(* Logix 5000 project; controller ASI 1769-L16ER-BB1B rev 32.11; software revision 32.01 *)

TASK MainTask (continuous, watchdog 500 ms) : MainProgram

MODULES
   Local : 1769-L16ER-BB1B (PointIO 0, rev 32.11)
      asidualgateway : vendor 57 type 12 code 393 (Ethernet 192.168.137.15, rev 2.8, StandardDataDriven RPI 10 ms)
           asidualgateway:I1.Data[51]   // LDS 31-16 [Net 2]
           asidualgateway:I1.Data[0].4   // F0
           asidualgateway:I1.Data[0].5   // F1
           asidualgateway:I1.Data[0].6   // F2
           asidualgateway:I1.Data[0].7   // F3
           asidualgateway:I1.Data[16].4   // F0
           asidualgateway:I1.Data[16].5   // F1
           asidualgateway:I1.Data[16].6   // F2
           asidualgateway:I1.Data[16].7   // F3
           asidualgateway:I1.Data[33]   // LDS 15-0
           asidualgateway:I1.Data[37]   // LPS 15-0
           asidualgateway:I1.Data[41]   // LAS 15-0
           asidualgateway:I1.Data[45]   // LPF 15-0
           asidualgateway:I1.Data[52]   // LDS 15B-0 [Net 2]
           asidualgateway:I1.Data[55]   // LPS 31-16 [Net 2]
           asidualgateway:I1.Data[56]   // LPS 15B-0 [Net 2]
           asidualgateway:I1.Data[2]   // 10A, 11A, 8A, 9A
           asidualgateway:I1.Data[0]   // 2A, 3A, Flags, 1A
           asidualgateway:I1.Data[3]   // 14A, 15A, 12A, 13A
           asidualgateway:I1.Data[4]   // 18A, 19A, 16A, 17A
           asidualgateway:I1.Data[5]   // 22A, 23A, 20A, 21A
           asidualgateway:I1.Data[6]   // 26A, 27A, 24A, 25A
           asidualgateway:I1.Data[7]   // 30A, 31A, 28A, 29A
           asidualgateway:I1.Data[10]   // 10B, 11B, 8B, 9B
           asidualgateway:I1.Data[32]   // Diagnostic Bits
           asidualgateway:I1.Data[32].14   // Power Fail
           asidualgateway:I1.Data[49].14   // Power Fail
           asidualgateway:I1.Data[50]   // LDS 15-0 [Net 2]
           asidualgateway:I1.Data[32].15   // Offline
           asidualgateway:I1.Data[54]   // LPS 15-0 [Net 2]
           asidualgateway:I1.Data[58]   // LAS 15-0 [Net 2]
           asidualgateway:I1.Data[62]   // LPF 15-0 [Net 2]
           asidualgateway:I1.Data[59]   // LAS 31-16 [Net 2]
           asidualgateway:I1.Data[49].15   // Offline
           asidualgateway:I1.Data[17]   // 6A, 7A, 4A, 5A [Net 2]
           asidualgateway:I1.Data[32].8   // Configuration Error
           asidualgateway:I1.Data[32].9   // LDS.0
           asidualgateway:I1.Data[32].0   // Peripheral Fault
           asidualgateway:I1.Data[8]   // 2B, 3B, 0, 1B
           asidualgateway:I1.Data[100]   // Analog, Adr 30, Channel 3 [Net 2]
           asidualgateway:I1.Data[34]   // LDS 31-16
           asidualgateway:I1.Data[49].9   // LDS.0
           asidualgateway:I1.Data[36]   // LDS 31B-16B
           asidualgateway:I1.Data[40]   // LPS 31B-16B
           asidualgateway:I1.Data[35]   // LDS 15B-0
           asidualgateway:I1.Data[44]   // LAS 31B-16B
           asidualgateway:I1.Data[48]   // LPF 31B-16B
           asidualgateway:I1.Data[38]   // LPS 31-16
           asidualgateway:I1.Data[101]   // Analog, Adr 30, Channel 4 [Net 2]
           asidualgateway:I1.Data[49].0   // Peripheral Fault
           asidualgateway:I1.Data[25]   // 6B, 7B, 4B, 5B [Net 2]
           asidualgateway:I1.Data[49]   // Diagnostic Bits [Net 2]
           asidualgateway:I1.Data[39]   // LPS 15B-0
           asidualgateway:I1.Data[42]   // LAS 31-16
           asidualgateway:I1.Data[1]   // 6A, 7A, 4A, 5A
           asidualgateway:I1.Data[43]   // LAS 15B-0
           asidualgateway:I1.Data[9]   // 6B, 7B, 4B, 5B
           asidualgateway:I1.Data[46]   // LPF 31-16
           asidualgateway:I1.Data[47]   // LPF 15B-0
           asidualgateway:I1.Data[60]   // LAS 15B-0 [Net 2]
           asidualgateway:I1.Data[11]   // 14B, 15B, 12B, 13B
           asidualgateway:I1.Data[53]   // LDS 31B-16B [Net 2]
           asidualgateway:I1.Data[57]   // LPS 31B-16B [Net 2]
           asidualgateway:I1.Data[12]   // 18B, 19B, 16B, 17B
           asidualgateway:I1.Data[24]   // 2B, 3B, 0, 1B [Net 2]
           asidualgateway:I1.Data[63]   // LPF 31-16 [Net 2]
           asidualgateway:I1.Data[13]   // 22B, 23B, 20B, 21B
           asidualgateway:I1.Data[61]   // LAS 31B-16B [Net 2]
           asidualgateway:I1.Data[65]   // LPF 31B-16B [Net 2]
           asidualgateway:I1.Data[14]   // 26B, 27B, 24B, 25B
           asidualgateway:I1.Data[64]   // LPF 15B-0 [Net 2]
           asidualgateway:I1.Data[15]   // 30B, 31B, 28B, 29B
           asidualgateway:I1.Data[18]   // 10A, 11A, 8A, 9A [Net 2]
           asidualgateway:I1.Data[19]   // 14A, 15A, 12A, 13A [Net 2]
           asidualgateway:I1.Data[20]   // 18A, 19A, 16A, 17A [Net 2]
           asidualgateway:I1.Data[21]   // 22A, 23A, 20A, 21A [Net 2]
           asidualgateway:I1.Data[22]   // 26A, 27A, 24A, 25A [Net 2]
           asidualgateway:I1.Data[23]   // 30A, 31A, 28A, 29A [Net 2]
           asidualgateway:I1.Data[26]   // 10B, 11B, 8B, 9B [Net 2]
           asidualgateway:I1.Data[27]   // 14B, 15B, 12B, 13B [Net 2]
           asidualgateway:I1.Data[28]   // 18B, 19B, 16B, 17B [Net 2]
           asidualgateway:I1.Data[29]   // 22B, 23B, 20B, 21B [Net 2]
           asidualgateway:I1.Data[30]   // 26B, 27B, 24B, 25B [Net 2]
           asidualgateway:I1.Data[31]   // 30B, 31B, 28B, 29B [Net 2]
           asidualgateway:I1.Data[32].1   // Earth/Ground Fault
           asidualgateway:I1.Data[49].8   // Configuration Error
           asidualgateway:I1.Data[49].13   // Normal Operation
           asidualgateway:I1.Data[32].10   // Automatic Addressing Not Possible
           asidualgateway:I1.Data[32].11   // Automatic Addressing Available
           asidualgateway:I1.Data[32].13   // Normal Operation
           asidualgateway:I1.Data[49].10   // Automatic Addressing Not Possible
           asidualgateway:I1.Data[49].11   // Automatic Addressing Available
           asidualgateway:I1.Data[32].12   // Configuration Mode Active
           asidualgateway:I1.Data[49].1   // Earth/Ground Fault
           asidualgateway:I1.Data[16]   // 2A, 3A, Flags, 1A [Net 2]
           asidualgateway:I1.Data[66]   // Analog, Adr 27, Channel 1
           asidualgateway:I1.Data[67]   // Analog, Adr 27, Channel 2
           asidualgateway:I1.Data[68]   // Analog, Adr 27, Channel 3
           asidualgateway:I1.Data[69]   // Analog, Adr 27, Channel 4
           asidualgateway:I1.Data[70]   // Analog, Adr 28, Channel 1
           asidualgateway:I1.Data[71]   // Analog, Adr 28, Channel 2
           asidualgateway:I1.Data[72]   // Analog, Adr 28, Channel 3
           asidualgateway:I1.Data[73]   // Analog, Adr 28, Channel 4
           asidualgateway:I1.Data[74]   // Analog, Adr 29, Channel 1
           asidualgateway:I1.Data[75]   // Analog, Adr 29, Channel 2
           asidualgateway:I1.Data[76]   // Analog, Adr 29, Channel 3
           asidualgateway:I1.Data[77]   // Analog, Adr 29, Channel 4
           asidualgateway:I1.Data[78]   // Analog, Adr 30, Channel 1
           asidualgateway:I1.Data[79]   // Analog, Adr 30, Channel 2
           asidualgateway:I1.Data[80]   // Analog, Adr 30, Channel 3
           asidualgateway:I1.Data[81]   // Analog, Adr 30, Channel 4
           asidualgateway:I1.Data[82]   // Analog, Adr 31, Channel 1
           asidualgateway:I1.Data[83]   // Analog, Adr 31, Channel 2
           asidualgateway:I1.Data[84]   // Analog, Adr 31, Channel 3
           asidualgateway:I1.Data[49].12   // Configuration Mode Active
           asidualgateway:I1.Data[86]   // Analog, Adr 27, Channel 1 [Net 2]
           asidualgateway:I1.Data[87]   // Analog, Adr 27, Channel 2 [Net 2]
           asidualgateway:I1.Data[88]   // Analog, Adr 27, Channel 3 [Net 2]
           asidualgateway:I1.Data[89]   // Analog, Adr 27, Channel 4 [Net 2]
           asidualgateway:I1.Data[90]   // Analog, Adr 28, Channel 1 [Net 2]
           asidualgateway:I1.Data[91]   // Analog, Adr 28, Channel 2 [Net 2]
           asidualgateway:I1.Data[92]   // Analog, Adr 28, Channel 3 [Net 2]
           asidualgateway:I1.Data[93]   // Analog, Adr 28, Channel 4 [Net 2]
           asidualgateway:I1.Data[94]   // Analog, Adr 29, Channel 1 [Net 2]
           asidualgateway:I1.Data[95]   // Analog, Adr 29, Channel 2 [Net 2]
           asidualgateway:I1.Data[96]   // Analog, Adr 29, Channel 3 [Net 2]
           asidualgateway:I1.Data[97]   // Analog, Adr 29, Channel 4 [Net 2]
           asidualgateway:I1.Data[98]   // Analog, Adr 30, Channel 1 [Net 2]
           asidualgateway:I1.Data[102]   // Analog, Adr 31, Channel 1 [Net 2]
           asidualgateway:I1.Data[103]   // Analog, Adr 31, Channel 2 [Net 2]
           asidualgateway:I1.Data[104]   // Analog, Adr 31, Channel 3 [Net 2]
           asidualgateway:I1.Data[105]   // Analog, Adr 31, Channel 4 [Net 2]
           asidualgateway:I1.Data[85]   // Analog, Adr 31, Channel 4
           asidualgateway:I1.Data[99]   // Analog, Adr 30, Channel 2 [Net 2]
           asidualgateway:O1.Data[2]   // 10A, 11A, 8A, 9A
           asidualgateway:O1.Data[3]   // 14A, 15A, 12A, 13A
           asidualgateway:O1.Data[4]   // 18A, 19A, 16A, 17A
           asidualgateway:O1.Data[5]   // 22A, 23A, 20A, 21A
           asidualgateway:O1.Data[6]   // 26A, 27A, 24A, 25A
           asidualgateway:O1.Data[7]   // 30A, 31A, 28A, 29A
           asidualgateway:O1.Data[10]   // 10B, 11B, 8B, 9B
           asidualgateway:O1.Data[71]   // Analog, Adr 31, Channel 4 [Net 2]
           asidualgateway:O1.Data[68]   // Analog, Adr 31, Channel 1 [Net 2]
           asidualgateway:O1.Data[65]   // Analog, Adr 30, Channel 2 [Net 2]
           asidualgateway:O1.Data[59]   // Analog, Adr 28, Channel 4 [Net 2]
           asidualgateway:O1.Data[19]   // 14A, 15A, 12A, 13A [Net 2]
           asidualgateway:O1.Data[70]   // Analog, Adr 31, Channel 3 [Net 2]
           asidualgateway:O1.Data[0]   // 2A, 3A, 0, 1A
           asidualgateway:O1.Data[8]   // 2B, 3B, 0, 1B
           asidualgateway:O1.Data[69]   // Analog, Adr 31, Channel 2 [Net 2]
           asidualgateway:O1.Data[60]   // Analog, Adr 29, Channel 1 [Net 2]
           asidualgateway:O1.Data[66]   // Analog, Adr 30, Channel 3 [Net 2]
           asidualgateway:O1.Data[61]   // Analog, Adr 29, Channel 2 [Net 2]
           asidualgateway:O1.Data[20]   // 18A, 19A, 16A, 17A [Net 2]
           asidualgateway:O1.Data[1]   // 6A, 7A, 4A, 5A
           asidualgateway:O1.Data[9]   // 6B, 7B, 4B, 5B
           asidualgateway:O1.Data[16]   // 2A, 3A, 0, 1A [Net 2]
           asidualgateway:O1.Data[24]   // 2B, 3B, 0, 1B [Net 2]
           asidualgateway:O1.Data[14]   // 26B, 27B, 24B, 25B
           asidualgateway:O1.Data[15]   // 30B, 31B, 28B, 29B
           asidualgateway:O1.Data[11]   // 14B, 15B, 12B, 13B
           asidualgateway:O1.Data[12]   // 18B, 19B, 16B, 17B
           asidualgateway:O1.Data[13]   // 22B, 23B, 20B, 21B
           asidualgateway:O1.Data[67]   // Analog, Adr 30, Channel 4 [Net 2]
           asidualgateway:O1.Data[62]   // Analog, Adr 29, Channel 3 [Net 2]
           asidualgateway:O1.Data[17]   // 6A, 7A, 4A, 5A [Net 2]
           asidualgateway:O1.Data[63]   // Analog, Adr 29, Channel 4 [Net 2]
           asidualgateway:O1.Data[64]   // Analog, Adr 30, Channel 1 [Net 2]
           asidualgateway:O1.Data[18]   // 10A, 11A, 8A, 9A [Net 2]
           asidualgateway:O1.Data[25]   // 6B, 7B, 4B, 5B [Net 2]
           asidualgateway:O1.Data[26]   // 10B, 11B, 8B, 9B [Net 2]
           asidualgateway:O1.Data[32]   // Analog, Adr 27, Channel 1
           asidualgateway:O1.Data[33]   // Analog, Adr 27, Channel 2
           asidualgateway:O1.Data[34]   // Analog, Adr 27, Channel 3
           asidualgateway:O1.Data[35]   // Analog, Adr 27, Channel 4
           asidualgateway:O1.Data[36]   // Analog, Adr 28, Channel 1
           asidualgateway:O1.Data[37]   // Analog, Adr 28, Channel 2
           asidualgateway:O1.Data[38]   // Analog, Adr 28, Channel 3
           asidualgateway:O1.Data[39]   // Analog, Adr 28, Channel 4
           asidualgateway:O1.Data[40]   // Analog, Adr 29, Channel 1
           asidualgateway:O1.Data[41]   // Analog, Adr 29, Channel 2
           asidualgateway:O1.Data[42]   // Analog, Adr 29, Channel 3
           asidualgateway:O1.Data[43]   // Analog, Adr 29, Channel 4
           asidualgateway:O1.Data[44]   // Analog, Adr 30, Channel 1
           asidualgateway:O1.Data[45]   // Analog, Adr 30, Channel 2
           asidualgateway:O1.Data[46]   // Analog, Adr 30, Channel 3
           asidualgateway:O1.Data[47]   // Analog, Adr 30, Channel 4
           asidualgateway:O1.Data[21]   // 22A, 23A, 20A, 21A [Net 2]
           asidualgateway:O1.Data[22]   // 26A, 27A, 24A, 25A [Net 2]
           asidualgateway:O1.Data[23]   // 30A, 31A, 28A, 29A [Net 2]
           asidualgateway:O1.Data[27]   // 14B, 15B, 12B, 13B [Net 2]
           asidualgateway:O1.Data[28]   // 18B, 19B, 16B, 17B [Net 2]
           asidualgateway:O1.Data[29]   // 22B, 23B, 20B, 21B [Net 2]
           asidualgateway:O1.Data[30]   // 26B, 27B, 24B, 25B [Net 2]
           asidualgateway:O1.Data[31]   // 30B, 31B, 28B, 29B [Net 2]
           asidualgateway:O1.Data[48]   // Analog, Adr 31, Channel 1
           asidualgateway:O1.Data[49]   // Analog, Adr 31, Channel 2
           asidualgateway:O1.Data[50]   // Analog, Adr 31, Channel 3
           asidualgateway:O1.Data[51]   // Analog, Adr 31, Channel 4
           asidualgateway:O1.Data[52]   // Analog, Adr 27, Channel 1 [Net 2]
           asidualgateway:O1.Data[53]   // Analog, Adr 27, Channel 2 [Net 2]
           asidualgateway:O1.Data[54]   // Analog, Adr 27, Channel 3 [Net 2]
           asidualgateway:O1.Data[55]   // Analog, Adr 27, Channel 4 [Net 2]
           asidualgateway:O1.Data[56]   // Analog, Adr 28, Channel 1 [Net 2]
           asidualgateway:O1.Data[57]   // Analog, Adr 28, Channel 2 [Net 2]
           asidualgateway:O1.Data[58]   // Analog, Adr 28, Channel 3 [Net 2]
      Discrete_IO : Embedded (PointIO 1, rev 32.11, Output RPI 20 ms)
END_MODULES

TYPE CTT2Command :
STRUCT
   Address : SINT;   // 1-31=1A-31A or 32-62= 31B-62B
   Command : SINT;   // 18=Read Venddor Specific Object
   Object : SINT;
   Length : SINT;
END_STRUCT
END_TYPE

TYPE Get_Member :
STRUCT
   Address : SINT;   // 1-31 = Address 1A-31A, 32-62 = Address 1B-31B
   Null : SINT;
END_STRUCT
END_TYPE

TYPE PF_Parameters :
STRUCT
   ADR_1A : SINT;
   ADR_2A : SINT;
   ADR_3A : SINT;
   ADR_4A : SINT;
   ADR_5A : SINT;
   ADR_6A : SINT;
   ADR_7A : SINT;
   ADR_8A : SINT;
   ADR_9A : SINT;
   ADR_10A : SINT;
   ADR_11A : SINT;
   ADR_12A : SINT;
   ADR_13A : SINT;
   ADR_14A : SINT;
   ADR_15A : SINT;
   ADR_16A : SINT;
   ADR_17A : SINT;
   ADR_18A : SINT;
   ADR_19A : SINT;
   ADR_20A : SINT;
   ADR_21A : SINT;
   ADR_22A : SINT;
   ADR_23A : SINT;
   ADR_24A : SINT;
   ADR_25A : SINT;
   ADR_26A : SINT;
   ADR_27A : SINT;
   ADR_28A : SINT;
   ADR_29A : SINT;
   ADR_30A : SINT;
   ADR_31A : SINT;
   ADR_1B : SINT;
   ADR_2B : SINT;
   ADR_3B : SINT;
   ADR_4B : SINT;
   ADR_5B : SINT;
   ADR_6B : SINT;
   ADR_7B : SINT;
   ADR_8B : SINT;
   ADR_9B : SINT;
   ADR_10B : SINT;
   ADR_11B : SINT;
   ADR_12B : SINT;
   ADR_13B : SINT;
   ADR_14B : SINT;
   ADR_15B : SINT;
   ADR_16B : SINT;
   ADR_17B : SINT;
   ADR_18B : SINT;
   ADR_19B : SINT;
   ADR_20B : SINT;
   ADR_21B : SINT;
   ADR_22B : SINT;
   ADR_23B : SINT;
   ADR_24B : SINT;
   ADR_25B : SINT;
   ADR_26B : SINT;
   ADR_27B : SINT;
   ADR_28B : SINT;
   ADR_29B : SINT;
   ADR_30B : SINT;
   ADR_31B : SINT;
END_STRUCT
END_TYPE

TYPE PF_Safety_Monitor_Diagnostics :
STRUCT
   NA : SINT;
   NA1 : SINT;
   NA2 : SINT;
   Status : SINT;   // Bit 0=Mode(0-config, 1=protect) Bit 4 Status S12 Bit 5 Status S21 Bit 6 Status S32 Bit 7 Status S41
   OSSD_2_1 : SINT;
   OSSD_4_3 : SINT;
   OSSD_6_5 : SINT;
   OSSD_8_7 : SINT;
   OSSD_10_9 : SINT;
   OSSD_12_11 : SINT;
   OSSD_14_13 : SINT;
   OSSD_16_15 : SINT;
   Device_Index_Present : SINT[32];   // Indexes that are present from 0 to 255
   Device_Index_Color : SINT[128];   // Two Indexes per byte, bits 0-3 device 1, bits 4-7 device 2
END_STRUCT
END_TYPE

TYPE Set_Parameter :
STRUCT
   Address : SINT;   // 1-31=Address 1-31, 32-62=Address 1B-31B
   Parameter : SINT;   // Parameter to Set
END_STRUCT
END_TYPE

TYPE Set_Ramp :
STRUCT
   Address : SINT;   // 1-31=Address 1-31, 32-62=Address 1B-31B
   Ramp : SINT;   // 0=No Ramp, 1=50ms, 2=100ms, 3=200ms, 4=300ms, 5=500ms, 6=1s, 7=1.5s
END_STRUCT
END_TYPE

ADD_ON_INSTRUCTION PF_Safety_Diag_KE5   (* revision 1.0, vendor Pepperl+Fuchs *)
// Reads diagnostics from a safety monitor on a VBg-EP1-KE5...
VAR_INPUT
   Trigger : BOOL; {visible}
   Safety_Monitor_Address : SINT; {visible}   // The address the safety monitor has been set to. Use 0 for Internal safety monitors
   ASi_Network : SINT; {visible}   // Which AS-i network is mailbox command being sent to. 0/1 is network 1, 2 is network 2
   Object : SINT; {visible}
END_VAR
VAR_OUTPUT
   EN : BOOL; {access Read Only, visible}   // Instruction is enabled
   DN : BOOL; {access Read Only, visible}   // DN bit, When on the instruction has completed. Check ER bit for Error
   ER : BOOL; {access Read Only, visible}   // If the DN bit is on and ER bit is off then command was successful. If ER bit is on then check status byte
END_VAR
VAR_IN_OUT
   ReadStringCmdMSG : MESSAGE; {required}
   ReadStringResponseMSG : MESSAGE; {required}
   Source : SINT[4]; {required}
   Destination : SINT[256]; {required}
END_VAR
VAR_OUTPUT
   State_of_OSSD_1 : SINT; {access Read Only, visible}   // 0 Green 1 Green flashing 2 Yellow 3 Yellow flashing 4 Red 5 Red flashing 6 Grey (OSSD not used) 7 Reserved
   State_of_OSSD_2 : SINT; {access Read Only, visible}   // 0 Green 1 Green flashing 2 Yellow 3 Yellow flashing 4 Red 5 Red flashing 6 Grey (OSSD not used) 7 Reserved
   State_of_OSSD_3 : SINT; {access Read Only, visible}   // 0 Green 1 Green flashing 2 Yellow 3 Yellow flashing 4 Red 5 Red flashing 6 Grey (OSSD not used) 7 Reserved
   State_of_OSSD_4 : SINT; {access Read Only, visible}   // 0 Green 1 Green flashing 2 Yellow 3 Yellow flashing 4 Red 5 Red flashing 6 Grey (OSSD not used) 7 Reserved
   State_of_OSSD_5 : SINT; {access Read Only, visible}   // 0 Green 1 Green flashing 2 Yellow 3 Yellow flashing 4 Red 5 Red flashing 6 Grey (OSSD not used) 7 Reserved
   State_of_OSSD_6 : SINT; {access Read Only, visible}   // 0 Green 1 Green flashing 2 Yellow 3 Yellow flashing 4 Red 5 Red flashing 6 Grey (OSSD not used) 7 Reserved
   State_of_OSSD_7 : SINT; {access Read Only, visible}   // 0 Green 1 Green flashing 2 Yellow 3 Yellow flashing 4 Red 5 Red flashing 6 Grey (OSSD not used) 7 Reserved
   State_of_OSSD_8 : SINT; {access Read Only, visible}   // 0 Green 1 Green flashing 2 Yellow 3 Yellow flashing 4 Red 5 Red flashing 6 Grey (OSSD not used) 7 Reserved
   State_of_OSSD_9 : SINT; {access Read Only, visible}   // 0 Green 1 Green flashing 2 Yellow 3 Yellow flashing 4 Red 5 Red flashing 6 Grey (OSSD not used) 7 Reserved
   State_of_OSSD_10 : SINT; {access Read Only, visible}   // 0 Green 1 Green flashing 2 Yellow 3 Yellow flashing 4 Red 5 Red flashing 6 Grey (OSSD not used) 7 Reserved
   State_of_OSSD_11 : SINT; {access Read Only, visible}   // 0 Green 1 Green flashing 2 Yellow 3 Yellow flashing 4 Red 5 Red flashing 6 Grey (OSSD not used) 7 Reserved
   State_of_OSSD_12 : SINT; {access Read Only, visible}   // 0 Green 1 Green flashing 2 Yellow 3 Yellow flashing 4 Red 5 Red flashing 6 Grey (OSSD not used) 7 Reserved
   State_of_OSSD_13 : SINT; {access Read Only, visible}   // 0 Green 1 Green flashing 2 Yellow 3 Yellow flashing 4 Red 5 Red flashing 6 Grey (OSSD not used) 7 Reserved
   State_of_OSSD_14 : SINT; {access Read Only, visible}   // 0 Green 1 Green flashing 2 Yellow 3 Yellow flashing 4 Red 5 Red flashing 6 Grey (OSSD not used) 7 Reserved
   State_of_OSSD_15 : SINT; {access Read Only, visible}   // 0 Green 1 Green flashing 2 Yellow 3 Yellow flashing 4 Red 5 Red flashing 6 Grey (OSSD not used) 7 Reserved
   State_of_OSSD_16 : SINT; {access Read Only, visible}   // 0 Green 1 Green flashing 2 Yellow 3 Yellow flashing 4 Red 5 Red flashing 6 Grey (OSSD not used) 7 Reserved
END_VAR
VAR_IN_OUT
   Device_Presence : SINT[16]; {required}   // 1 bit for each device object used in safety monitor program
   Index_Colors : SINT[128]; {required}   // An array of diagnostic colors 0 Green 1 Green flashing 2 Yellow 3 Yellow flashing 4 Red 5 Red flashing 6 Gray
END_VAR
VAR_OUTPUT
   Last_Index : DINT; {access Read Only, visible}   // The number of diagnostic indexes returned
   Mode : BOOL; {access Read Only, visible}   // Off=Config Mode, On=Protected mode
   S12 : BOOL; {access Read Only, visible}
   S21 : BOOL; {access Read Only, visible}
   S32 : BOOL; {visible}
   S41 : BOOL; {visible}
   Error_Code : INT; {access Read Only, visible}
END_VAR
VAR
   oneshot : DINT; {access None}
   Null : SINT; {access None}
   Indexcolors : DINT; {access None}
   index0 : DINT; {access None}
   index1 : DINT; {access None}
   Color_Pointer : DINT; {access None}
   watchdog : TIMER := (PRE := 8000); {access None}
END_VAR

ROUTINE Logic   (* ladder *)
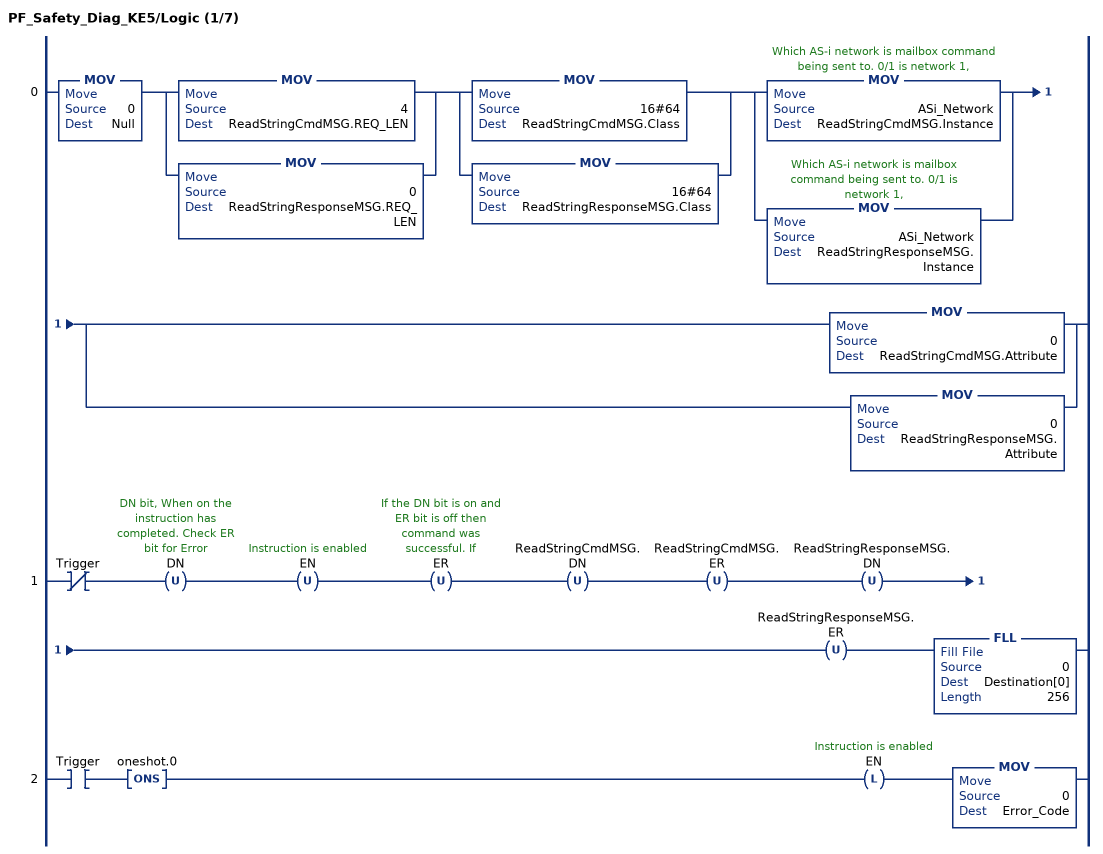
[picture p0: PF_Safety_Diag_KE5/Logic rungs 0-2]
   0: MOV(0,Null)[MOV(4,ReadStringCmdMSG.REQ_LEN) ,MOV(0,ReadStringResponseMSG.REQ_LEN) ][MOV(16#64,ReadStringCmdMSG.Class) ,MOV(16#64,ReadStringResponseMSG.Class) ][MOV(ASi_Network,ReadStringCmdMSG.Instance) ,MOV(ASi_Network,ReadStringResponseMSG.Instance) ][MOV(0,ReadStringCmdMSG.Attribute) ,MOV(0,ReadStringResponseMSG.Attribute) ];
   1: XIO(Trigger)OTU(DN)OTU(EN)OTU(ER)OTU(ReadStringCmdMSG.DN)OTU(ReadStringCmdMSG.ER)OTU(ReadStringResponseMSG.DN)OTU(ReadStringResponseMSG.ER)FLL(0,Destination[0],256);
   2: XIC(Trigger)ONS(oneshot.0)OTL(EN)MOV(0,Error_Code);
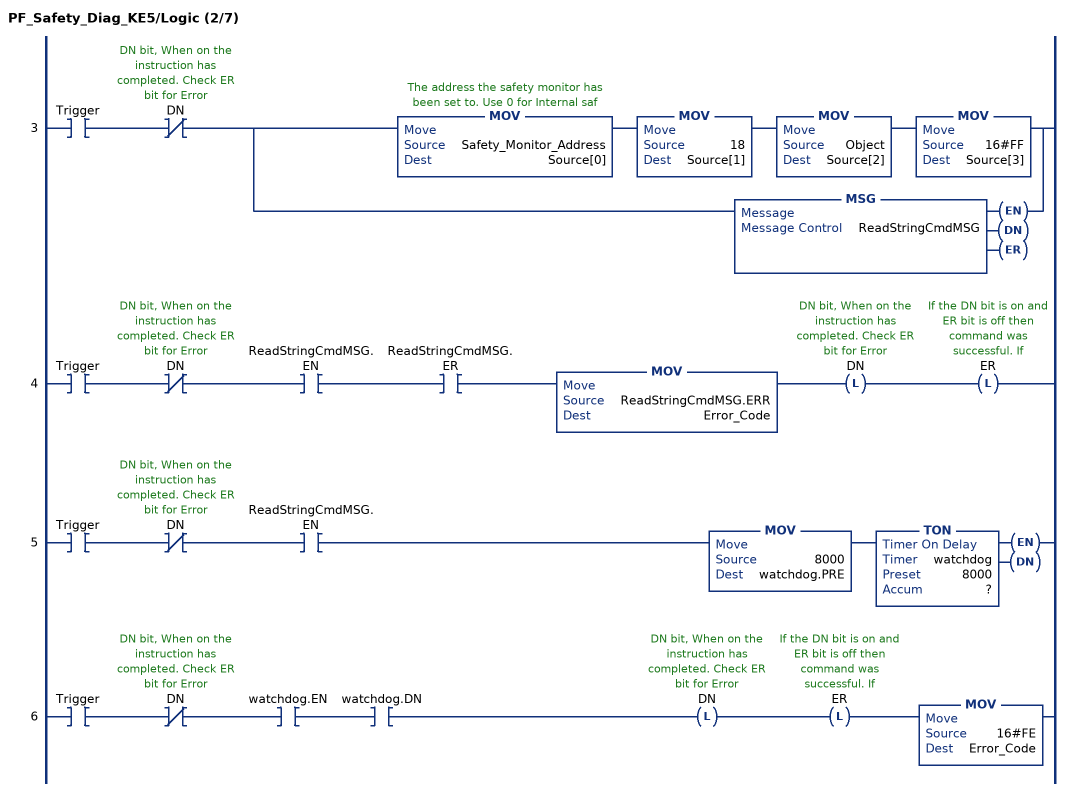
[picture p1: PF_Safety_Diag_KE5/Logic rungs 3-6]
   3: XIC(Trigger)XIO(DN)[MOV(Safety_Monitor_Address,Source[0]) MOV(18,Source[1]) MOV(Object,Source[2]) MOV(16#FF,Source[3]) ,MSG(ReadStringCmdMSG) ];
   4: XIC(Trigger)XIO(DN)XIC(ReadStringCmdMSG.EN)XIC(ReadStringCmdMSG.ER)MOV(ReadStringCmdMSG.ERR,Error_Code)OTL(DN)OTL(ER);
   5: XIC(Trigger)XIO(DN)XIC(ReadStringCmdMSG.EN)MOV(8000,watchdog.PRE)TON(watchdog,?,?);
   6: XIC(Trigger)XIO(DN)XIC(watchdog.EN)XIC(watchdog.DN)OTL(DN)OTL(ER)MOV(16#FE,Error_Code);
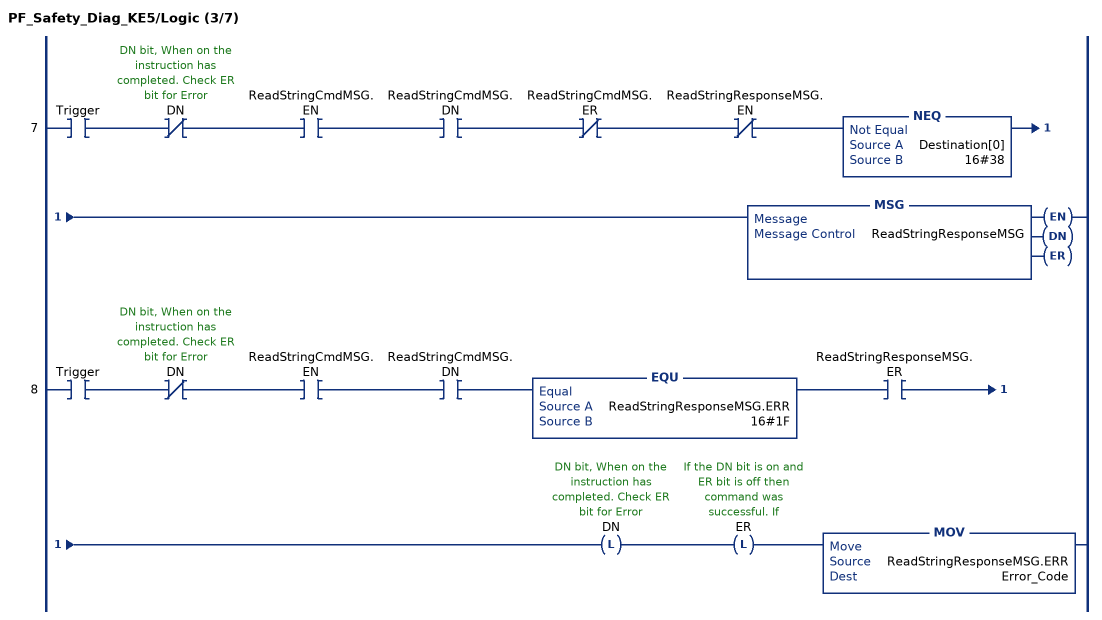
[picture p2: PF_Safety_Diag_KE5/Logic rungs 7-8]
   7: XIC(Trigger)XIO(DN)XIC(ReadStringCmdMSG.EN)XIC(ReadStringCmdMSG.DN)XIO(ReadStringCmdMSG.ER)XIO(ReadStringResponseMSG.EN)NEQ(Destination[0],16#38)MSG(ReadStringResponseMSG);
   8: XIC(Trigger)XIO(DN)XIC(ReadStringCmdMSG.EN)XIC(ReadStringCmdMSG.DN)EQU(ReadStringResponseMSG.ERR,16#1F)XIC(ReadStringResponseMSG.ER)OTL(DN)OTL(ER)MOV(ReadStringResponseMSG.ERR,Error_Code);
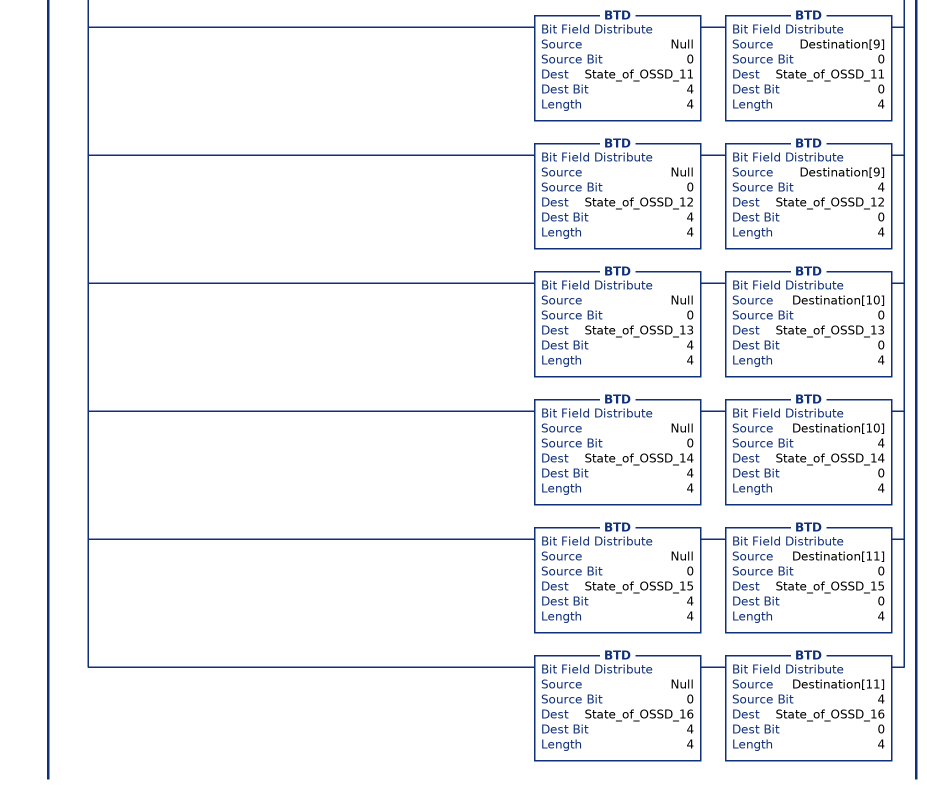
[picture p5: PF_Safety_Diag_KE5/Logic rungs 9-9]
   9: XIC(Trigger)XIO(DN)XIC(ReadStringResponseMSG.DN)XIO(ReadStringResponseMSG.ER)EQU(Destination[0],16#38)ONS(oneshot.2)[[XIC(Destination[3].0) OTL(Mode) ,XIO(Destination[3].0) OTU(Mode) ,XIC(Destination[3].4) OTL(S12) ,XIO(Destination[3].4) OTU(S12) ,XIC(Destination[3].5) OTL(S21) ,XIO(Destination[3].5) OTU(S21) ,XIC(Destination[3].6) OTL(S32) ,XIO(Destination[3].6) OTU(S32) ,XIC(Destination[3].7) OTL(S41) ,XIO(Destination[3].7) OTU(S41) ] ,BTD(Null,0,State_of_OSSD_1,4,4) BTD(Destination[4],0,State_of_OSSD_1,0,4) ,BTD(Null,0,State_of_OSSD_2,4,4) BTD(Destination[4],4,State_of_OSSD_2,0,4) ,BTD(Null,0,State_of_OSSD_3,4,4) BTD(Destination[5],0,State_of_OSSD_3,0,4) ,BTD(Null,0,State_of_OSSD_4,4,4) BTD(Destination[5],4,State_of_OSSD_4,0,4) ,BTD(Null,0,State_of_OSSD_5,4,4) BTD(Destination[6],0,State_of_OSSD_5,0,4) ,BTD(Null,0,State_of_OSSD_6,4,4) BTD(Destination[6],4,State_of_OSSD_6,0,4) ,BTD(Null,0,State_of_OSSD_7,4,4) BTD(Destination[7],0,State_of_OSSD_7,0,4) ,BTD(Null,0,State_of_OSSD_8,4,4) BTD(Destination[7],4,State_of_OSSD_8,0,4) ,BTD(Null,0,State_of_OSSD_9,4,4) BTD(Destination[8],0,State_of_OSSD_9,0,4) ,BTD(Null,0,State_of_OSSD_10,4,4) BTD(Destination[8],4,State_of_OSSD_10,0,4) ,BTD(Null,0,State_of_OSSD_11,4,4) BTD(Destination[9],0,State_of_OSSD_11,0,4) ,BTD(Null,0,State_of_OSSD_12,4,4) BTD(Destination[9],4,State_of_OSSD_12,0,4) ,BTD(Null,0,State_of_OSSD_13,4,4) BTD(Destination[10],0,State_of_OSSD_13,0,4) ,BTD(Null,0,State_of_OSSD_14,4,4) BTD(Destination[10],4,State_of_OSSD_14,0,4) ,BTD(Null,0,State_of_OSSD_15,4,4) BTD(Destination[11],0,State_of_OSSD_15,0,4) ,BTD(Null,0,State_of_OSSD_16,4,4) BTD(Destination[11],4,State_of_OSSD_16,0,4) ];
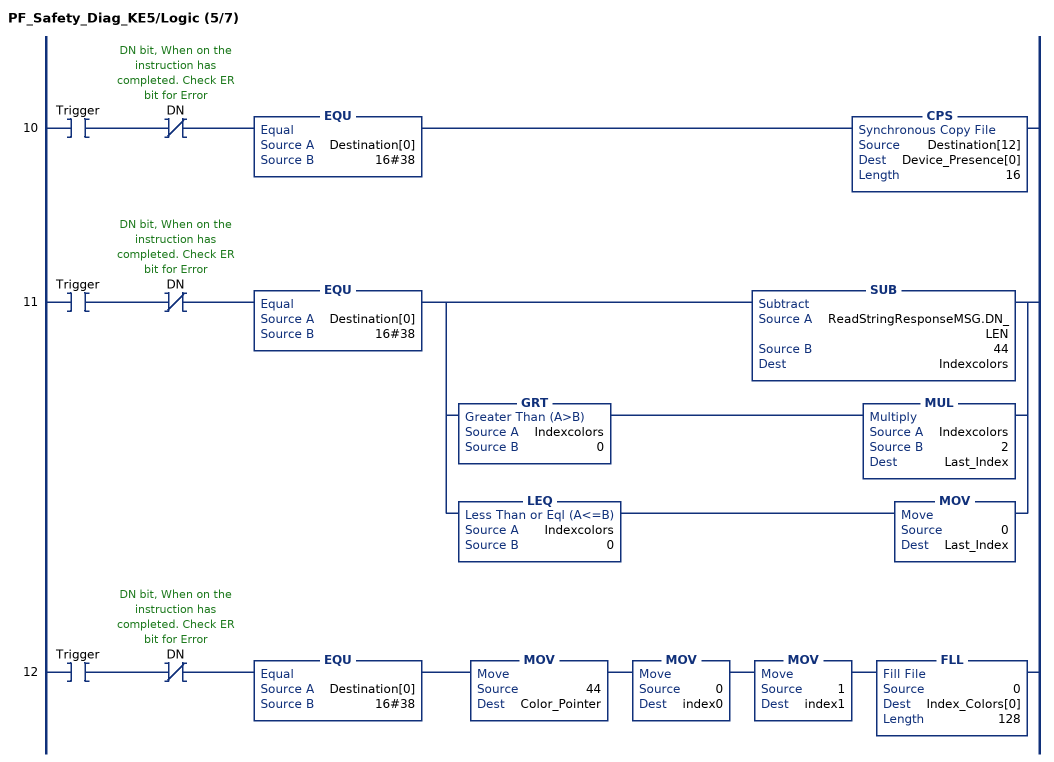
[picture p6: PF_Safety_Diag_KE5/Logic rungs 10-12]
   10: XIC(Trigger)XIO(DN)EQU(Destination[0],16#38)CPS(Destination[12],Device_Presence[0],16);
   11: XIC(Trigger)XIO(DN)EQU(Destination[0],16#38)[SUB(ReadStringResponseMSG.DN_LEN,44,Indexcolors) ,GRT(Indexcolors,0) MUL(Indexcolors,2,Last_Index) ,LEQ(Indexcolors,0) MOV(0,Last_Index) ];
   12: XIC(Trigger)XIO(DN)EQU(Destination[0],16#38)MOV(44,Color_Pointer)MOV(0,index0)MOV(1,index1)FLL(0,Index_Colors[0],128);
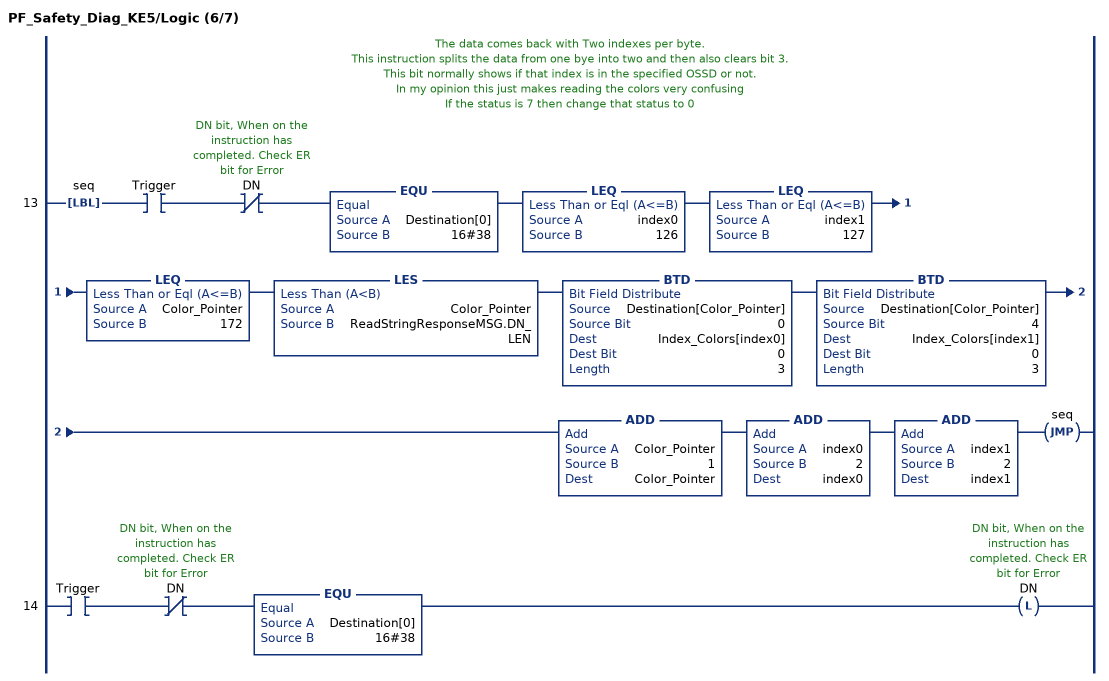
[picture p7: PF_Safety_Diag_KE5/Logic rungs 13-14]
   // The data comes back with Two indexes per byte.
   // This instruction splits the data from one bye into two and then also clears bit 3.
   // This bit normally shows if that index is in the specified OSSD or not.
   // In my opinion this just makes reading the colors very confusing
   // If the status is 7 then change that status to 0
   13: LBL(seq)XIC(Trigger)XIO(DN)EQU(Destination[0],16#38)LEQ(index0,126)LEQ(index1,127)LEQ(Color_Pointer,172)LES(Color_Pointer,ReadStringResponseMSG.DN_LEN)BTD(Destination[Color_Pointer],0,Index_Colors[index0],0,3)BTD(Destination[Color_Pointer],4,Index_Colors[index1],0,3)ADD(Color_Pointer,1,Color_Pointer)ADD(index0,2,index0)ADD(index1,2,index1)JMP(seq);
   14: XIC(Trigger)XIO(DN)EQU(Destination[0],16#38)OTL(DN);
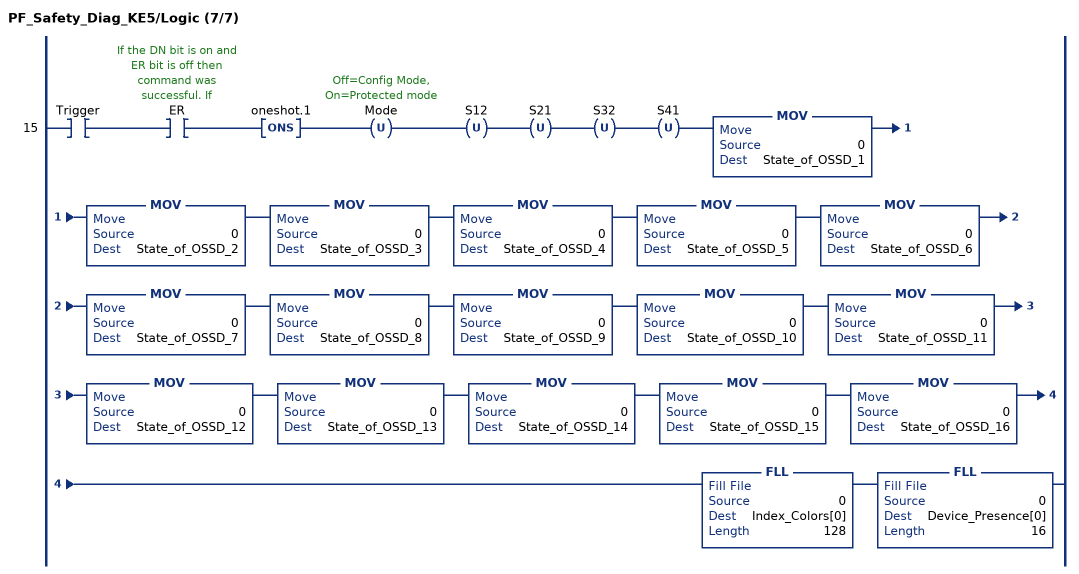
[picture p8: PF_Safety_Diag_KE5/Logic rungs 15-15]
   15: XIC(Trigger)XIC(ER)ONS(oneshot.1)OTU(Mode)OTU(S12)OTU(S21)OTU(S32)OTU(S41)MOV(0,State_of_OSSD_1)MOV(0,State_of_OSSD_2)MOV(0,State_of_OSSD_3)MOV(0,State_of_OSSD_4)MOV(0,State_of_OSSD_5)MOV(0,State_of_OSSD_6)MOV(0,State_of_OSSD_7)MOV(0,State_of_OSSD_8)MOV(0,State_of_OSSD_9)MOV(0,State_of_OSSD_10)MOV(0,State_of_OSSD_11)MOV(0,State_of_OSSD_12)MOV(0,State_of_OSSD_13)MOV(0,State_of_OSSD_14)MOV(0,State_of_OSSD_15)MOV(0,State_of_OSSD_16)FLL(0,Index_Colors[0],128)FLL(0,Device_Presence[0],16);
END_ROUTINE
END_ADD_ON_INSTRUCTION

VAR_GLOBAL   (* controller tags *)
   Actual_Parameter_Return : SINT := 7;
   Actual_Parameters : PF_Parameters;
   Address_1_Running : BOOL := 1;
   colors : SINT[128] := ([2] := 4, [3] := 4, [4] := 4, [5] := 6);
   Command_Status : DINT;
   Data : SINT[100] := ([0] := 18, [1] := 7, [2] := 42);
   Data1 : SINT[100];
   data45 : ALIAS FOR asidualgateway:I1.Data[0];
   data46 : ALIAS FOR asidualgateway:I1;
   delaytimer : TIMER := (PRE := 3000);
   Destination : SINT[256];
   device_presence : SINT[16] := ([0] := 31);
   GetCTT2Response : BOOL;
   GetResponse : MESSAGE;
        MessageParameters(ServiceCode := 16#0039, DestinationTag := Safety_Monitor, ...)
   Member_of_ASi_Network : Get_Member := (Address := 1);
   MSG_1 : MESSAGE;
        MessageParameters(ServiceCode := 16#000e, DestinationTag := Actual_Parameters, ...)
   MSG_2 : MESSAGE;
        MessageParameters(ServiceCode := 16#0032, LocalElement := Param_Send_Data, DestinationTag := Param_Echo, ...)
   MSG_3 : MESSAGE;
        MessageParameters(ServiceCode := 16#0018, LocalElement := Member_of_ASi_Network, DestinationTag := Actual_Parameter_Return, ...)
   MSG_4 : MESSAGE;
        MessageParameters(ServiceCode := 16#0005, LocalElement := ResetData2, ...)
   MSG_5 : MESSAGE;
        MessageParameters(ServiceCode := 16#000e, DestinationTag := Permanent_Parameters, ...)
   MSG_6 : MESSAGE;
        MessageParameters(ServiceCode := 16#0010, LocalElement := Permanent_Parameters, ...)
   oneshot : DINT;
   Param_Echo : SINT := 15;
   Param_Send_Data : Set_Parameter := (Address := 1, Parameter := 7);
   Parameters : PF_Parameters;
   Permanent_Parameters : PF_Parameters;
   Read_All_Parameters : BOOL;
   Read_All_Perm_Param : BOOL;
   Read_One_Parameter : BOOL := 1;
   ReadCmdMSG : MESSAGE;
        MessageParameters(ServiceCode := 16#0038, LocalElement := source, DestinationTag := Destination, ...)
   ReadCTT2String : BOOL := 1;
   ReadResponseMSG : MESSAGE;
        MessageParameters(ServiceCode := 16#0039, LocalElement := source, DestinationTag := Destination, ...)
   ReadSafetyDiagnostics : CTT2Command := (Address := 27, Command := 18, Object := 7, Length := -1);
   Reset : BOOL;
   ResetData2 : SINT;
   ResetToggle : BOOL := 1;
   Resonse : DINT;
   Response : SINT;
   Safety_Monitor : PF_Safety_Monitor_Diagnostics := (NA := 56, NA1 := 27, NA2 := 82, Status := 1, OSSD_2_1 := 70, OSSD_4_3 := 102, OSSD_6_5 := 102, OSSD_8_7 := 102, OSSD_10_9 := 102, OSSD_12_11 := 102, OSSD_14_13 := 102, OSSD_16_15 := 102, Device_Index_Present[0] := 31, Device_Index_Color[1] := 68, Device_Index_Color[2] := 100);
        .NA1   // Address string came from
        .NA   // Service Code string request came from
   SendCommand : MESSAGE;
        MessageParameters(ServiceCode := 16#0038, LocalElement := ReadSafetyDiagnostics, DestinationTag := Command_Status, ...)
   SetMotorRamp : BOOL;
   SetRampData : Set_Parameter;
   SetRampMSG : MESSAGE;
        MessageParameters(ServiceCode := 16#0033, LocalElement := SetRampParameters, DestinationTag := Response, ...)
   SetRampParameters : Set_Ramp := (Address := 12, Ramp := 1);
   source : SINT[4] := ([0] := 27, [1] := 18, [2] := 7, [3] := -1);
   TestKE5Safety : PF_Safety_Diag_KE5 := (Safety_Monitor_Address := 27, ASi_Network := 1, Object := 7, State_of_OSSD_1 := 6, State_of_OSSD_2 := 4, State_of_OSSD_3 := 6, State_of_OSSD_4 := 6, State_of_OSSD_5 := 6, State_of_OSSD_6 := 6, State_of_OSSD_7 := 6, State_of_OSSD_8 := 6, State_of_OSSD_9 := 6, State_of_OSSD_10 := 6, State_of_OSSD_11 := 6, State_of_OSSD_12 := 6, State_of_OSSD_13 := 6, State_of_OSSD_14 := 6, State_of_OSSD_15 := 6, State_of_OSSD_16 := 6, Last_Index := 6, Mode := 1);
   Write_All_Perm_Param : BOOL;
   Write_Parameter : BOOL;
END_VAR

PROGRAM MainProgram   (* main routine MainRoutine *)

ROUTINE MainRoutine   (* ladder *)
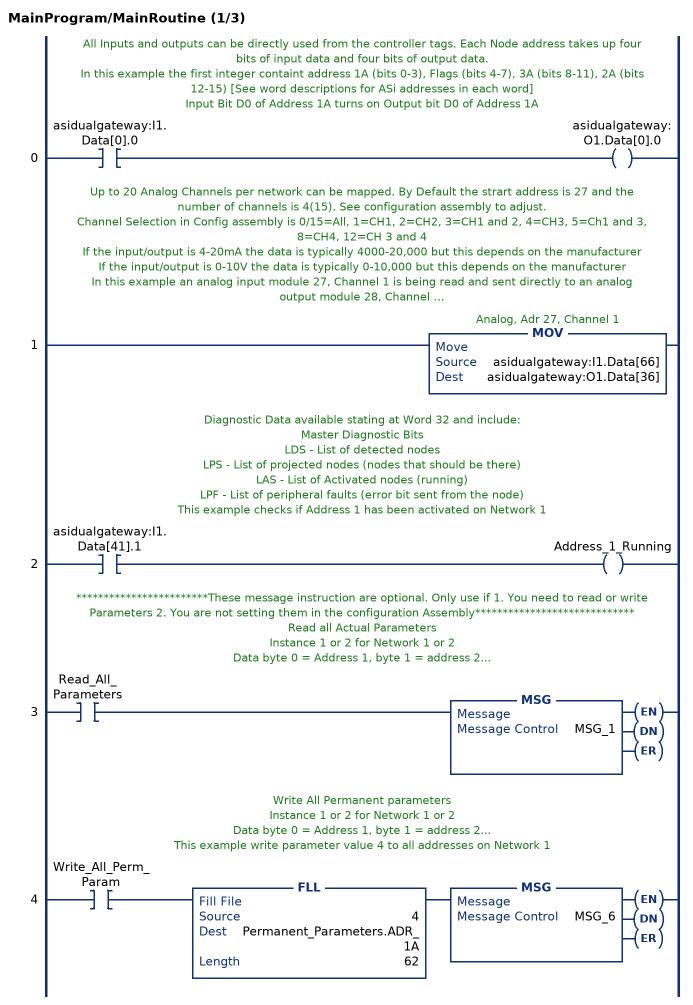
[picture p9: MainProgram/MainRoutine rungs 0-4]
   // All Inputs and outputs can be directly used from the controller tags. Each Node address takes up four bits of input data and four bits of output data.
   // In this example the first integer containt address 1A (bits 0-3), Flags (bits 4-7), 3A (bits 8-11), 2A (bits 12-15) [See word descriptions for ASi addresses in each word]
   // Input Bit D0 of Address 1A turns on Output bit D0 of Address 1A
   0: XIC(asidualgateway:I1.Data[0].0)OTE(asidualgateway:O1.Data[0].0);
   // Up to 20 Analog Channels per network can be mapped. By Default the strart address is 27 and the number of channels is 4(15). See configuration assembly to adjust.
   // Channel Selection in Config assembly is 0/15=All, 1=CH1, 2=CH2, 3=CH1 and 2, 4=CH3, 5=Ch1 and 3, 8=CH4, 12=CH 3 and 4
   // If the input/output is 4-20mA the data is typically 4000-20,000 but this depends on the manufacturer
   // If the input/output is 0-10V the data is typically 0-10,000 but this depends on the manufacturer
   // In this example an analog input module 27, Channel 1 is being read and sent directly to an analog output module 28, Channel 1
   // A typical analog module is an input or output module but not both.
   1: MOV(asidualgateway:I1.Data[66],asidualgateway:O1.Data[36]);
   // Diagnostic Data available stating at Word 32 and include:
   // Master Diagnostic Bits
   // LDS - List of detected nodes
   // LPS - List of projected nodes (nodes that should be there)
   // LAS - List of Activated nodes (running)
   // LPF - List of peripheral faults (error bit sent from the node)
   // This example checks if Address 1 has been activated on Network 1
   2: XIC(asidualgateway:I1.Data[41].1)OTE(Address_1_Running);
   // ************************These message instruction are optional. Only use if 1. You need to read or write Parameters 2. You are not setting them in the configuration Assembly*****************************
   // Read all Actual Parameters
   // Instance 1 or 2 for Network 1 or 2
   // Data byte 0 = Address 1, byte 1 = address 2...
   3: XIC(Read_All_Parameters)MSG(MSG_1);
   // Write All Permanent parameters
   // Instance 1 or 2 for Network 1 or 2
   // Data byte 0 = Address 1, byte 1 = address 2...
   // This example write parameter value 4 to all addresses on Network 1
   4: XIC(Write_All_Perm_Param)FLL(4,Permanent_Parameters.ADR_1A,62)MSG(MSG_6);
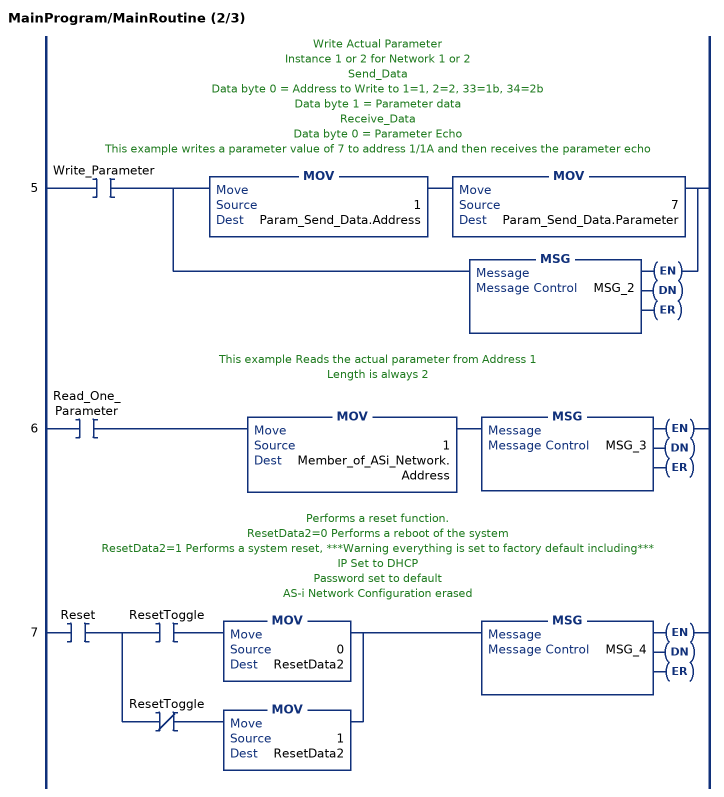
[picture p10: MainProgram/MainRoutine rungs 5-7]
   // Write Actual Parameter
   // Instance 1 or 2 for Network 1 or 2
   // Send_Data
   // Data byte 0 = Address to Write to 1=1, 2=2, 33=1b, 34=2b
   // Data byte 1 = Parameter data
   // Receive_Data
   // Data byte 0 = Parameter Echo
   // This example writes a parameter value of 7 to address 1/1A and then receives the parameter echo
   5: XIC(Write_Parameter)[MOV(1,Param_Send_Data.Address) MOV(7,Param_Send_Data.Parameter) ,MSG(MSG_2) ];
   // This example Reads the actual parameter from Address 1
   // Length is always 2
   6: XIC(Read_One_Parameter)MOV(1,Member_of_ASi_Network.Address)MSG(MSG_3);
   // Performs a reset function.
   // ResetData2=0 Performs a reboot of the system
   // ResetData2=1 Performs a system reset, ***Warning everything is set to factory default including***
   // IP Set to DHCP
   // Password set to default
   // AS-i Network Configuration erased
   7: XIC(Reset)[XIC(ResetToggle) MOV(0,ResetData2) ,XIO(ResetToggle) MOV(1,ResetData2) ]MSG(MSG_4);
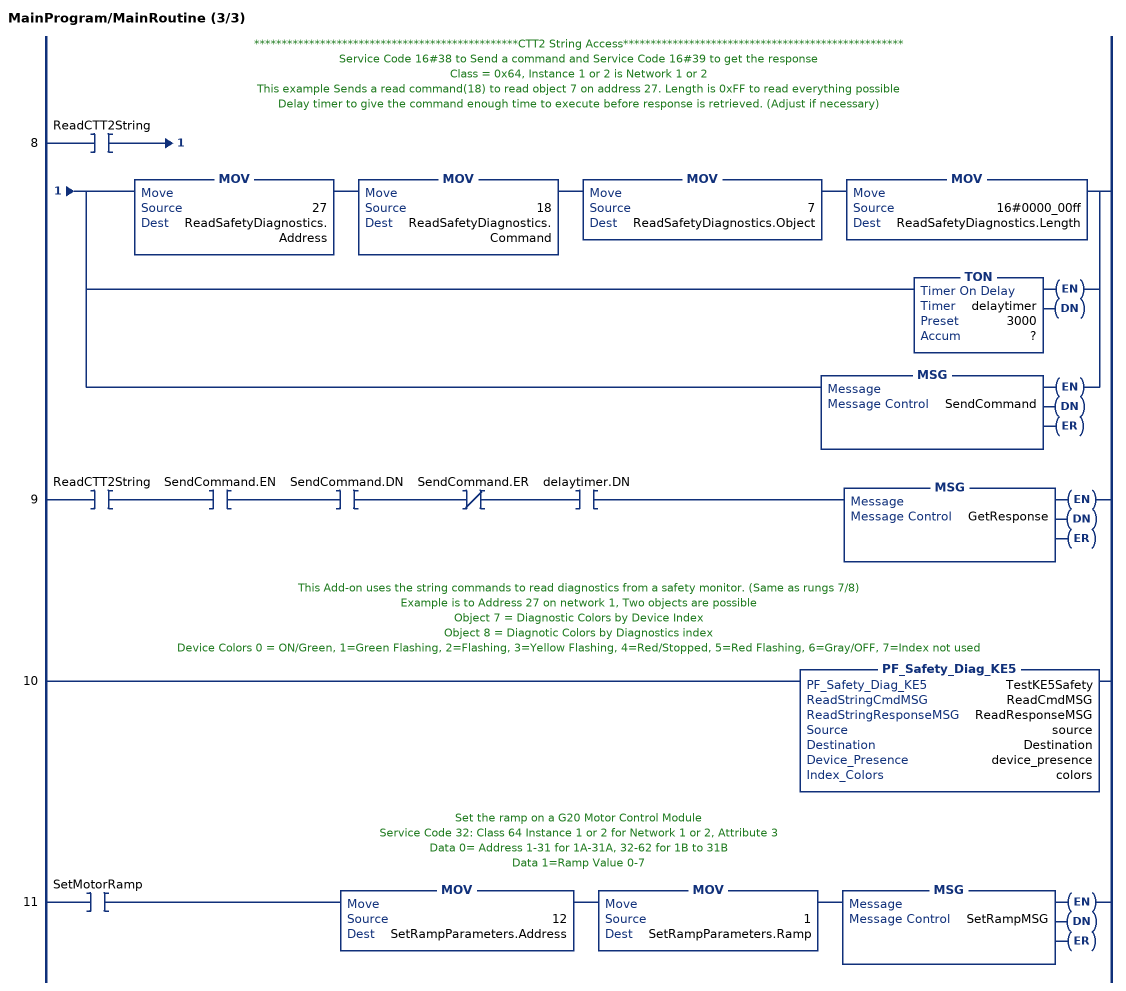
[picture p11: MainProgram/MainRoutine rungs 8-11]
   // ************************************************CTT2 String Access***************************************************
   // Service Code 16#38 to Send a command and Service Code 16#39 to get the response
   // Class = 0x64, Instance 1 or 2 is Network 1 or 2
   // This example Sends a read command(18) to read object 7 on address 27. Length is 0xFF to read everything possible
   // Delay timer to give the command enough time to execute before response is retrieved. (Adjust if necessary)
   8: XIC(ReadCTT2String)[MOV(27,ReadSafetyDiagnostics.Address) MOV(18,ReadSafetyDiagnostics.Command) MOV(7,ReadSafetyDiagnostics.Object) MOV(16#0000_00ff,ReadSafetyDiagnostics.Length) ,TON(delaytimer,?,?) ,MSG(SendCommand) ];
   9: XIC(ReadCTT2String)XIC(SendCommand.EN)XIC(SendCommand.DN)XIO(SendCommand.ER)XIC(delaytimer.DN)MSG(GetResponse);
   // This Add-on uses the string commands to read diagnostics from a safety monitor. (Same as rungs 7/8)
   // Example is to Address 27 on network 1, Two objects are possible
   // Object 7 = Diagnostic Colors by Device Index
   // Object 8 = Diagnotic Colors by Diagnostics index
   // Device Colors 0 = ON/Green, 1=Green Flashing, 2=Flashing, 3=Yellow Flashing, 4=Red/Stopped, 5=Red Flashing, 6=Gray/OFF, 7=Index not used
   10: PF_Safety_Diag_KE5(TestKE5Safety,ReadCmdMSG,ReadResponseMSG,source,Destination,device_presence,colors);
   // Set the ramp on a G20 Motor Control Module
   // Service Code 32: Class 64 Instance 1 or 2 for Network 1 or 2, Attribute 3
   // Data 0= Address 1-31 for 1A-31A, 32-62 for 1B to 31B
   // Data 1=Ramp Value 0-7
   11: XIC(SetMotorRamp)MOV(12,SetRampParameters.Address)MOV(1,SetRampParameters.Ramp)MSG(SetRampMSG);
END_ROUTINE
END_PROGRAM
